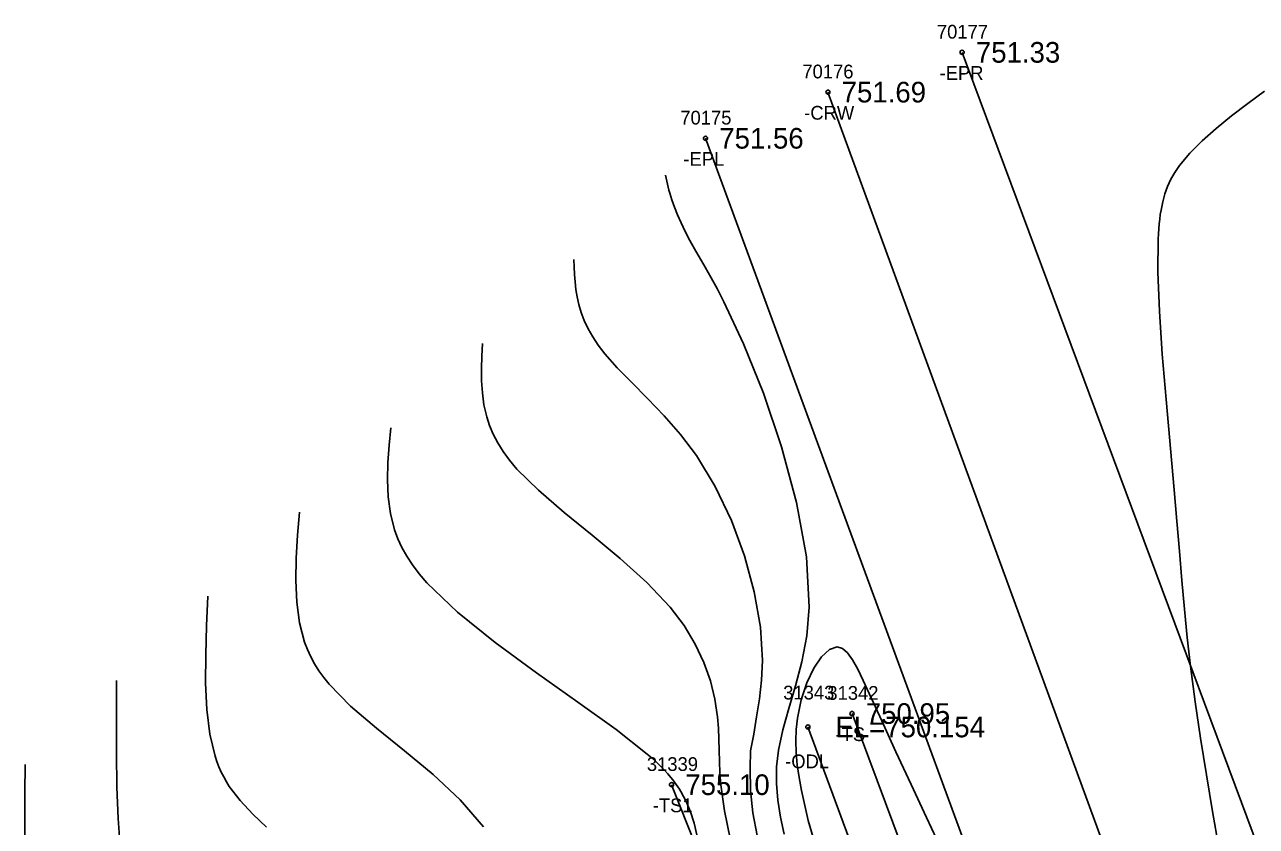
# Model space of a CAD drawing. Extents: x 1376587 to 1378239, y 1000335 to 1003031.
# Drawn here: x 1376610.3 to 1376699.8, y 1002972.6 to 1003030.9 of the extents above; entities that cross this region are included whole.
import ezdxf

# ---------------------------------------------------------------- set-up
doc = ezdxf.new("R2010")
doc.units = 0
for name, color, linetype in [('RD_DTM_BkLn1', 7, 'Continuous'), ('RD_DTM_BkLn2', 7, 'Continuous'), ('RD_DTM_BkLn_txCode', 7, 'Continuous'), ('RD_DTM_Major1', 7, 'Continuous'), ('RD_DTM_Minor1', 7, 'Continuous'), ('RD_EX_H2O', 7, 'Continuous'), ('RD_EX_H2O_txCode', 7, 'Continuous'), ('RD_EX_Road', 7, 'Continuous'), ('RD_EX_Road_txCode', 7, 'Continuous'), ('RD_EX_TX_H2O_ELEV', 7, 'Continuous'), ('RD_EX_TX_Misc_ELEV', 7, 'Continuous'), ('RD_EX_TX_Road_ELEV', 7, 'Continuous'), ('RD_HC_Survey_ELEV', 7, 'Continuous'), ('RD_HC_Survey_txCode', 7, 'Continuous'), ('RD_SMD_Locator', 7, 'Continuous')]:
    doc.layers.add(name, color=color, linetype=linetype)

msp = doc.modelspace()

# ---------------------------------------------------------------- linework, layer by layer
at = {"layer": 'RD_DTM_BkLn1'}
msp.add_lwpolyline([(1376777.121, 1002732.301), (1376776.775, 1002733.821), (1376754.908, 1002791.106), (1376734.245, 1002847.871), (1376712.479, 1002906.611), (1376690.983, 1002965.022), (1376668.656, 1003026.023)], dxfattribs=at)
at = {"layer": 'RD_DTM_BkLn2'}
for points in [[(1376885.612, 1002428.977), (1376889.779, 1002434.68), (1376874.693, 1002468.745), (1376852.186, 1002514.329), (1376831.795, 1002561.56), (1376809.955, 1002613.347), (1376792.968, 1002652.804), (1376775.328, 1002700.183), (1376756.387, 1002747.207), (1376739.797, 1002794.066), (1376723.095, 1002839.909), (1376704.947, 1002887.539), (1376687.765, 1002934.36), (1376670.41, 1002980.848)], [(1376885.61, 1002428.968), (1376881.3, 1002430.181), (1376863.125, 1002464.593), (1376838.707, 1002510.163), (1376821.819, 1002559.181), (1376802.886, 1002607.61), (1376786.807, 1002643.277), (1376765.505, 1002696.104), (1376748.394, 1002745.623), (1376732.066, 1002790.52), (1376713.537, 1002837.08), (1376692.706, 1002883.805), (1376675.418, 1002930.221), (1376657.289, 1002975.676)]]:
    msp.add_lwpolyline(points, dxfattribs=at)
at = {"layer": 'RD_DTM_Major1'}
msp.add_lwpolyline([(1376636.889, 1003001.619), (1376636.767, 1003000.351), (1376636.673, 1002999.089), (1376636.636, 1002997.837), (1376636.685, 1002996.6), (1376636.847, 1002995.384), (1376637.152, 1002994.193), (1376637.39, 1002993.553), (1376637.683, 1002992.918), (1376638.036, 1002992.285), (1376638.453, 1002991.65), (1376638.938, 1002991.008), (1376639.495, 1002990.358), (1376641.722, 1002988.222), (1376644.464, 1002986.02), (1376647.468, 1002983.819), (1376650.482, 1002981.687), (1376653.253, 1002979.692), (1376655.528, 1002977.902), (1376655.87, 1002977.602), (1376656.189, 1002977.31), (1376656.484, 1002977.025), (1376656.758, 1002976.746), (1376657.01, 1002976.472), (1376657.243, 1002976.202), (1376657.379, 1002976.032), (1376657.509, 1002975.864), (1376657.632, 1002975.695), (1376657.749, 1002975.527), (1376657.859, 1002975.359), (1376657.964, 1002975.19), (1376658.356, 1002974.455), (1376658.67, 1002973.692), (1376658.922, 1002972.892), (1376659.131, 1002972.044)], dxfattribs=at)
at = {"layer": 'RD_DTM_Minor1'}
for points in [[(1376700.388, 1003026.097), (1376699.18, 1003025.194), (1376698.003, 1003024.291), (1376696.888, 1003023.389), (1376695.865, 1003022.488), (1376694.966, 1003021.59), (1376694.222, 1003020.695), (1376693.882, 1003020.193), (1376693.595, 1003019.685), (1376693.357, 1003019.164), (1376693.161, 1003018.623), (1376693.002, 1003018.053), (1376692.876, 1003017.449), (1376692.824, 1003017.131), (1376692.778, 1003016.801), (1376692.739, 1003016.457), (1376692.706, 1003016.098), (1376692.68, 1003015.723), (1376692.659, 1003015.329), (1376692.642, 1003012.929), (1376692.756, 1003010.102), (1376692.967, 1003006.979), (1376693.24, 1003003.689), (1376693.831, 1002997.123), (1376694.027, 1002994.837), (1376694.21, 1002992.646), (1376694.391, 1002990.524), (1376694.579, 1002988.443), (1376694.786, 1002986.378), (1376695.021, 1002984.302), (1376695.362, 1002981.695), (1376695.75, 1002979.051), (1376696.174, 1002976.391), (1376696.622, 1002973.735), (1376697.083, 1002971.103)], [(1376656.84, 1003019.982), (1376656.937, 1003019.557), (1376656.988, 1003019.342), (1376657.042, 1003019.125), (1376657.1, 1003018.904), (1376657.163, 1003018.679), (1376657.316, 1003018.185), (1376657.5, 1003017.663), (1376657.72, 1003017.11), (1376657.978, 1003016.524), (1376658.28, 1003015.9), (1376658.63, 1003015.235), (1376658.966, 1003014.634), (1376659.738, 1003013.293), (1376660.168, 1003012.532), (1376660.623, 1003011.698), (1376661.1, 1003010.78), (1376662.522, 1003007.732), (1376663.964, 1003004.145), (1376665.293, 1003000.228), (1376666.379, 1002996.19), (1376667.089, 1002992.239), (1376667.293, 1002988.584), (1376667.119, 1002986.51), (1376666.766, 1002984.609), (1376666.308, 1002982.854), (1376665.82, 1002981.218), (1376665.377, 1002979.672), (1376665.054, 1002978.19), (1376664.919, 1002976.966), (1376664.909, 1002975.755), (1376665.009, 1002974.545), (1376665.205, 1002973.323), (1376665.482, 1002972.078)], [(1376650.19, 1003013.861), (1376650.21, 1003013.316), (1376650.238, 1003012.771), (1376650.278, 1003012.226), (1376650.339, 1003011.681), (1376650.427, 1003011.136), (1376650.547, 1003010.59), (1376650.721, 1003010.004), (1376650.946, 1003009.416), (1376651.225, 1003008.825), (1376651.563, 1003008.227), (1376651.965, 1003007.623), (1376652.435, 1003007.011), (1376653.346, 1003005.985), (1376654.401, 1003004.909), (1376655.552, 1003003.756), (1376656.75, 1003002.504), (1376657.947, 1003001.127), (1376659.095, 1002999.602), (1376660.464, 1002997.352), (1376661.639, 1002994.891), (1376662.595, 1002992.307), (1376663.306, 1002989.688), (1376663.746, 1002987.122), (1376663.892, 1002984.696), (1376663.828, 1002983.27), (1376663.676, 1002981.917), (1376663.477, 1002980.618), (1376663.27, 1002979.356), (1376663.024, 1002978.14), (1376662.997, 1002976.87), (1376663.022, 1002975.263), (1376663.204, 1002973.634), (1376663.518, 1002971.986)], [(1376643.539, 1003007.74), (1376643.498, 1003006.838), (1376643.473, 1003005.938), (1376643.48, 1003005.044), (1376643.535, 1003004.157), (1376643.653, 1003003.28), (1376643.851, 1003002.415), (1376644.058, 1003001.781), (1376644.323, 1003001.153), (1376644.65, 1003000.526), (1376645.044, 1002999.898), (1376645.509, 1002999.264), (1376646.05, 1002998.623), (1376647.611, 1002997.078), (1376649.476, 1002995.476), (1376651.506, 1002993.821), (1376653.561, 1002992.117), (1376655.502, 1002990.37), (1376657.188, 1002988.583), (1376658.196, 1002987.249), (1376659.007, 1002985.904), (1376659.639, 1002984.558), (1376660.109, 1002983.22), (1376660.433, 1002981.897), (1376660.627, 1002980.599), (1376660.693, 1002979.794), (1376660.729, 1002978.994), (1376660.749, 1002978.19), (1376660.77, 1002977.373), (1376660.806, 1002976.536), (1376660.871, 1002975.669), (1376661.136, 1002973.781), (1376661.558, 1002971.767)], [(1376630.238, 1002995.498), (1376630.104, 1002993.812), (1376630.003, 1002992.145), (1376629.97, 1002990.516), (1376630.038, 1002988.941), (1376630.241, 1002987.441), (1376630.612, 1002986.033), (1376630.817, 1002985.495), (1376631.056, 1002984.973), (1376631.332, 1002984.463), (1376631.646, 1002983.963), (1376631.999, 1002983.47), (1376632.394, 1002982.981), (1376633.954, 1002981.396), (1376635.829, 1002979.795), (1376637.875, 1002978.147), (1376639.95, 1002976.422), (1376641.91, 1002974.587), (1376643.613, 1002972.611)], [(1376623.588, 1002989.377), (1376623.488, 1002987.223), (1376623.42, 1002985.107), (1376623.415, 1002983.065), (1376623.506, 1002981.134), (1376623.723, 1002979.352), (1376624.1, 1002977.755), (1376624.235, 1002977.354), (1376624.385, 1002976.969), (1376624.55, 1002976.598), (1376624.73, 1002976.239), (1376624.926, 1002975.893), (1376625.137, 1002975.557), (1376625.93, 1002974.52), (1376626.846, 1002973.543), (1376627.838, 1002972.588)], [(1376676.908, 1002970.971), (1376675.824, 1002973.294), (1376674.705, 1002975.699), (1376673.604, 1002978.077), (1376672.572, 1002980.313), (1376671.661, 1002982.297), (1376671.222, 1002983.25), (1376670.823, 1002984.072), (1376670.449, 1002984.745), (1376670.087, 1002985.251), (1376669.722, 1002985.573), (1376669.341, 1002985.691), (1376668.777, 1002985.508), (1376668.195, 1002984.97), (1376667.632, 1002984.14), (1376667.126, 1002983.079), (1376666.717, 1002981.849), (1376666.442, 1002980.512), (1376666.357, 1002979.694), (1376666.329, 1002978.856), (1376666.355, 1002977.996), (1376666.432, 1002977.11), (1376666.557, 1002976.196), (1376666.726, 1002975.25), (1376667.232, 1002973.072), (1376667.894, 1002970.772)], [(1376616.937, 1002983.256), (1376616.926, 1002980.581), (1376616.932, 1002977.972), (1376616.97, 1002975.493), (1376617.058, 1002973.21), (1376617.211, 1002971.187)], [(1376610.287, 1002977.135), (1376610.282, 1002975.088), (1376610.274, 1002973.035), (1376610.257, 1002970.97)]]:
    msp.add_lwpolyline(points, dxfattribs=at)
at = {"layer": 'RD_EX_H2O'}
msp.add_lwpolyline([(1376884.041, 1002432.097), (1376867.958, 1002466.268), (1376845.473, 1002511.575), (1376827.215, 1002560.377), (1376806.483, 1002611.175), (1376788.408, 1002651.649), (1376772.823, 1002694.383), (1376753.279, 1002747.214), (1376736.654, 1002792.885), (1376719.204, 1002838.909), (1376701.081, 1002887.179), (1376684.577, 1002932.846), (1376667.201, 1002979.872)], dxfattribs=at)
at = {"layer": 'RD_EX_Road'}
for points in [[(1376786.564, 1002736.458), (1376786.096, 1002737.56), (1376764.686, 1002794.995), (1376744.066, 1002850.85), (1376722.323, 1002910.048), (1376701.332, 1002967.349), (1376678.413, 1003028.916)], [(1376768.457, 1002728.838), (1376767.881, 1002730.045), (1376746.195, 1002787.097), (1376725.105, 1002844.978), (1376703.802, 1002902.776), (1376682.094, 1002961.906), (1376659.76, 1003022.669)]]:
    msp.add_lwpolyline(points, dxfattribs=at)
at = {"layer": 'RD_SMD_Locator'}
for centre in [(1376678.413, 1003028.916), (1376668.656, 1003026.023), (1376659.76, 1003022.669), (1376670.41, 1002980.848), (1376667.201, 1002979.872), (1376657.289, 1002975.676)]:
    msp.add_circle(centre, 0.15, dxfattribs=at)

# ---------------------------------------------------------------- texts
at = {"layer": 'RD_DTM_BkLn_txCode'}
for s, p in [('31342', (1376668.615, 1002981.848)), ('-TS', (1376669.205, 1002978.848)), ('31339', (1376655.494, 1002976.676)), ('-TS1', (1376655.919, 1002973.676))]:
    msp.add_text(s, height=1, dxfattribs=at).set_placement(p)
at = {"layer": 'RD_EX_H2O_txCode'}
for s, p in [('31343', (1376665.406, 1002981.872)), ('-ODL', (1376665.547, 1002976.872))]:
    msp.add_text(s, height=1, dxfattribs=at).set_placement(p)
at = {"layer": 'RD_EX_Road_txCode'}
for s, p in [('70177', (1376676.578, 1003029.916)), ('-EPR', (1376676.775, 1003026.916)), ('70175', (1376657.925, 1003023.669)), ('-EPL', (1376658.146, 1003020.669))]:
    msp.add_text(s, height=1, dxfattribs=at).set_placement(p)
at = {"layer": 'RD_EX_TX_H2O_ELEV'}
msp.add_text('EL=750.154', height=1.5, dxfattribs=at).set_placement((1376669.201, 1002979.122))
at = {"layer": 'RD_EX_TX_Misc_ELEV'}
for s, p in [('750.95', (1376671.41, 1002980.098)), ('755.10', (1376658.289, 1002974.926))]:
    msp.add_text(s, height=1.5, dxfattribs=at).set_placement(p)
at = {"layer": 'RD_EX_TX_Road_ELEV'}
for s, p in [('751.33', (1376679.413, 1003028.166)), ('751.56', (1376660.76, 1003021.919))]:
    msp.add_text(s, height=1.5, dxfattribs=at).set_placement(p)
at = {"layer": 'RD_HC_Survey_ELEV'}
msp.add_text('751.69', height=1.5, dxfattribs=at).set_placement((1376669.656, 1003025.273))
at = {"layer": 'RD_HC_Survey_txCode'}
for s, p in [('70176', (1376666.798, 1003027.023)), ('-CRW', (1376666.932, 1003024.023))]:
    msp.add_text(s, height=1, dxfattribs=at).set_placement(p)

doc.saveas('drawing.dxf')
